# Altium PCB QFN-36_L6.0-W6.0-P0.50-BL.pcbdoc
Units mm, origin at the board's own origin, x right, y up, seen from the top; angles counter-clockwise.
Board outline 19.86 x 19.5 mm, 2 copper layers (Top Layer, Bottom Layer); 1 components, 0 nets, 37 pads, 25 vias.
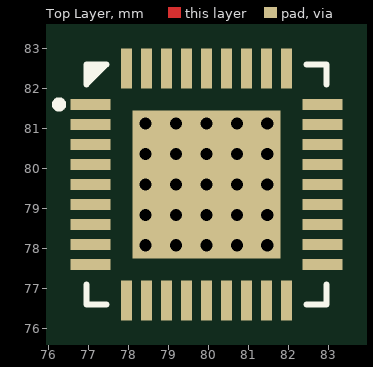
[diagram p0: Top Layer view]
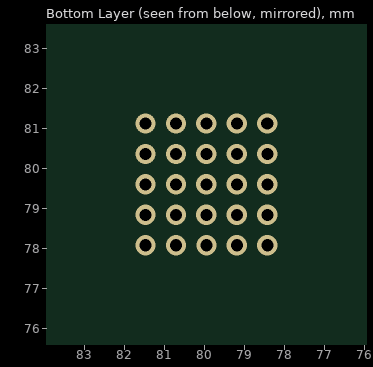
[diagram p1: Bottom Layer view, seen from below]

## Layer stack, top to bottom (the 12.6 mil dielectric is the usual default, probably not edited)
Top Layer: signal copper (thickness not stored)
Dielectric: dielectric 0.32, FR-4, Dk 4.8
Bottom Layer: signal copper (thickness not stored)

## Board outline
89.71,69.85 69.85,69.85 69.85,89.35 89.71,89.35

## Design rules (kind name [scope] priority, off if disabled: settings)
BoardOutlineClearance safeClearance [All] p0: genericclearance=0.254 ignorepadtopadclearanceinfootprint=FALSE except(0: Arc-SplitContinuation Track-SplitContinuation SMDPad-SplitContinuation THPad-SplitContinuation Via-SplitContinuation Fill-SplitContinuation Poly-SplitContinuation Region-SplitContinuation Text-SplitContinuation; 0.152: Track-CutoutEdge SMDPad-CutoutEdge THPad-CutoutEdge Via-CutoutEdge Fill-CutoutEdge Region-CutoutEdge; 0.3: Track-OutlineEdge SMDPad-OutlineEdge THPad-OutlineEdge Via-OutlineEdge Fill-OutlineEdge Region-OutlineEdge Poly-OutlineEdge Text-OutlineEdge)
Clearance safeClearance [All] p1: gap=0.178 ignorepadtopadclearanceinfootprint=FALSE except(0.152: Track-Track Track-SMDPad SMDPad-SMDPad Track-THPad SMDPad-THPad THPad-THPad Track-Via SMDPad-Via THPad-Via Via-Via Track-Fill SMDPad-Fill THPad-Fill Via-Fill Fill-Fill Track-Region SMDPad-Region THPad-Region Via-Region Fill-Region Region-Region Track-Poly SMDPad-Poly THPad-Poly Via-Poly Fill-Poly Region-Poly Poly-Poly Track-Text SMDPad-Text THPad-Text Via-Text Fill-Text Region-Text Poly-Text Text-Text Track-Hole SMDPad-Hole THPad-Hole Via-Hole Fill-Hole Region-Hole Poly-Hole Text-Hole; 0.3: Track-Sheet SMDPad-Sheet THPad-Sheet Via-Sheet Fill-Sheet Region-Sheet Poly-Sheet Text-Sheet Sheet-Hole)
DiffPairsRouting differentialPair [All] p1: maxuncoupledlength=10 minlimit=6 maxlimit=6 mostfreqgap=6 toplayer_minwidth=5 toplayer_prefwidth=10 toplayer_maxwidth=100 bottomlayer_minwidth=5 bottomlayer_prefwidth=10 bottomlayer_maxwidth=100
PasteMaskExpansion pasteMaskExpansion [All] p1: expansion=0
PlaneConnect innerPlane [All] p1: planeconnectstyle=Relief reliefexpansion=0.508 reliefentries=4 reliefconductorwidth=0.254 reliefairgap=0.254
PolygonConnect copperRegion [All] p1: connectstyle=Relief reliefentries=4 reliefconductorwidth=10 polygonreliefangle="90 Angle" airgapwidth=10
RoutingVias viaSize [All] p1: viastyle="Through Hole" holewidth=12.0078 minholewidth=11.811 maxholewidth=236.2204 width=24.0158 minwidth=19.685 maxwidth=393.7008
SolderMaskExpansion solderMaskExpansion [All] p1: useseparateexpansions=TRUE expansion=2 expansionbottom=2
Width trackWidth [All] p1: maxlimit=100 minlimit=5 preferedwidth=10

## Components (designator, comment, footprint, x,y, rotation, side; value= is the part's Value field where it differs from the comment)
? "QFN-36_L6.0-W6.0-P0.50-BL-EP3.7" QFN-36_L6.0-W6.0-P0.50-BL-EP3.7 79.96,79.6 r0 top

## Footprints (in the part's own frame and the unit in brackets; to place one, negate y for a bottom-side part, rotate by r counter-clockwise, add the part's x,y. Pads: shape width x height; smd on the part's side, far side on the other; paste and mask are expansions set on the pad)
QFN-36_L6.0-W6.0-P0.50-BL-EP3.7 [mm]
  rect 1x0.28 smd: 1(-2.9,2) 2(-2.9,1.5) 3(-2.9,1) 4(-2.9,0.5) 5(-2.9,0) 6(-2.9,-0.5) 7(-2.9,-1) 8(-2.9,-1.5) 9(-2.9,-2) 19(2.9,-2) 20(2.9,-1.5) 21(2.9,-1) 22(2.9,-0.5) 23(2.9,0) 24(2.9,0.5) 25(2.9,1) 26(2.9,1.5) 27(2.9,2)
  rect 0.28x1 smd: 10(-2,-2.9) 11(-1.5,-2.9) 12(-1,-2.9) 13(-0.5,-2.9) 14(0,-2.9) 15(0.5,-2.9) 16(1,-2.9) 17(1.5,-2.9) 18(2,-2.9) 28(2,2.9) 29(1.5,2.9) 30(1,2.9) 31(0.5,2.9) 32(0,2.9) 33(-0.5,2.9) 34(-1,2.9) 35(-1.5,2.9) 36(-2,2.9)
  rect 3.7x3.7 smd: 37(0,0)
  silkscreen extent -3.76,-3 3,3

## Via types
v1: diameter 0.508, hole 0.305, Top Layer to Bottom Layer, 25 vias

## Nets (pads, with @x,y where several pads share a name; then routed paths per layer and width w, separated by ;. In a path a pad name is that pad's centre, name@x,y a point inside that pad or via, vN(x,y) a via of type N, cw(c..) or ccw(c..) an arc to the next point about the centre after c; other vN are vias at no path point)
pads on no net: ?.1 ?.2 ?.3 ?.4 ?.5 ?.6 ?.7 ?.8 ?.9 ?.10 ?.11 ?.12 ?.13 ?.14 ?.15 ?.16 ?.17 ?.18 ?.19 ?.20 ?.21 ?.22 ?.23 ?.24 ?.25 ?.26 ?.27 ?.28 ?.29 ?.30 ?.31 ?.32 ?.33 ?.34 ?.35 ?.36 ?.37
copper on no net:
  other v1: 78.436,78.077 79.197,78.077 79.959,78.077 80.721,78.077 81.483,78.077 78.436,78.839 79.198,78.839 79.959,78.839 80.721,78.839 81.483,78.838 78.436,79.6 79.198,79.6 79.959,79.6 80.721,79.6 81.483,79.6 78.436,80.362 79.198,80.362 79.959,80.362 80.721,80.362 81.483,80.362 78.436,81.124 79.198,81.124 79.959,81.124 80.721,81.124 81.483,81.124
